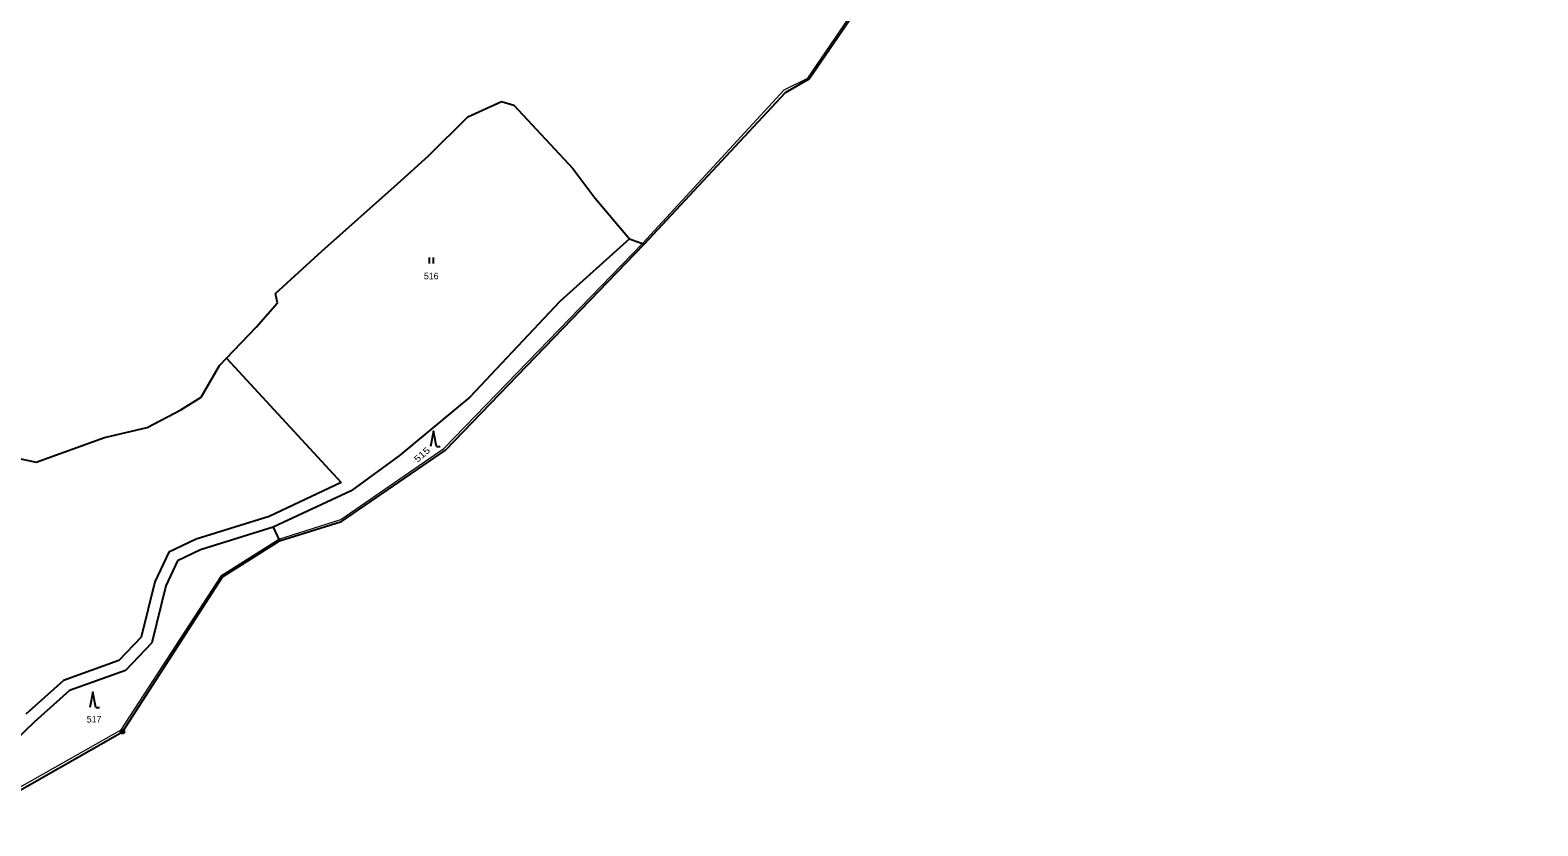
# Model space of a CAD drawing. Extents: x -653193 to -651624, y -1092017 to -1090260.
# Drawn here: x -652015.8 to -651624.2, y -1091342 to -1091135.1 of the extents above; entities that cross this region are included whole.
import ezdxf
from ezdxf.enums import TextEntityAlignment as Align

# ---------------------------------------------------------------- set-up
doc = ezdxf.new("R2010")
doc.units = 0
doc.header["$LTSCALE"] = 0.68
for name, color, linetype, lineweight in [('1', 7, 'Continuous', 25), ('3', 7, 'Continuous', 25), ('4', 7, 'Continuous', 13), ('8', 7, 'Continuous', 25)]:
    doc.layers.add(name, color=color, linetype=linetype, lineweight=lineweight)
doc.layers.add('2', color=7, linetype='Continuous')

msp = doc.modelspace()

# ---------------------------------------------------------------- linework, layer by layer
at = {"layer": '1'}
for p, q in [((-651813.51, -1091147.74), (-651741.09, -1091042.17)), ((-651819.63, -1091151.3), (-651813.51, -1091147.74)), ((-651856.36, -1091190.71), (-651819.63, -1091151.3)), ((-651902.14, -1091157.63), (-651893.36, -1091153.6)), ((-651893.36, -1091153.6), (-651890.18, -1091154.58)), ((-651890.18, -1091154.58), (-651874.87, -1091171.1)), ((-651912.35, -1091167.75), (-651902.14, -1091157.63)), ((-651920.38, -1091175.06), (-651912.35, -1091167.75)), ((-651874.87, -1091171.1), (-651869.11, -1091178.7)), ((-651940.03, -1091192.56), (-651920.38, -1091175.06)), ((-651869.11, -1091178.7), (-651860.16, -1091189.33)), ((-651907.97, -1091244.32), (-651856.36, -1091190.71)), ((-651860.16, -1091189.33), (-651878.25, -1091205.61)), ((-651860.16, -1091189.33), (-651856.36, -1091190.71)), ((-651952.13, -1091203.52), (-651940.03, -1091192.56)), ((-651957.1, -1091212.35), (-651951.61, -1091205.96)), ((-651951.61, -1091205.96), (-651952.13, -1091203.52)), ((-651878.25, -1091205.61), (-651901.63, -1091230.54)), ((-651964.83, -1091220.35), (-651957.1, -1091212.35)), ((-651971.44, -1091230.55), (-651966.66, -1091222.25)), ((-651966.66, -1091222.25), (-651964.83, -1091220.35)), ((-651964.83, -1091220.35), (-651935.01, -1091252.71)), ((-651985.46, -1091238.42), (-651976.7, -1091233.76)), ((-651976.7, -1091233.76), (-651971.44, -1091230.55)), ((-651901.63, -1091230.54), (-651919.86, -1091245.65)), ((-652014.28, -1091247.38), (-651996.53, -1091241)), ((-651996.53, -1091241), (-651985.46, -1091238.42)), ((-652025.75, -1091244.89), (-652014.28, -1091247.38)), ((-651934.93, -1091262.8), (-651907.97, -1091244.32)), ((-651919.86, -1091245.65), (-651932.45, -1091254.89)), ((-651935.01, -1091252.71), (-651953.76, -1091261.49)), ((-651932.45, -1091254.89), (-651952.68, -1091264.29)), ((-651953.76, -1091261.49), (-651972.71, -1091267.39)), ((-651952.68, -1091264.29), (-651971.61, -1091270.19)), ((-651952.68, -1091264.29), (-651951.09, -1091267.9)), ((-651951.09, -1091267.9), (-651934.93, -1091262.8)), ((-651972.71, -1091267.39), (-651979.84, -1091270.8)), ((-651965.88, -1091277.21), (-651951.09, -1091267.9)), ((-651979.84, -1091270.8), (-651983.45, -1091278.53)), ((-651977.58, -1091273.04), (-651980.61, -1091279.53)), ((-651971.61, -1091270.19), (-651977.58, -1091273.04)), ((-651991.83, -1091317.47), (-651965.88, -1091277.21)), ((-651983.45, -1091278.53), (-651986.97, -1091292.87)), ((-651980.61, -1091279.53), (-651984.25, -1091294.36)), ((-651986.97, -1091292.87), (-651992.78, -1091298.95)), ((-651984.25, -1091294.36), (-651991.1, -1091301.53)), ((-651992.78, -1091298.95), (-652007.17, -1091304.16)), ((-652016.85, -1091312.8), (-652007.17, -1091304.16)), ((-651991.1, -1091301.53), (-652005.6, -1091306.78)), ((-652005.6, -1091306.78), (-652014.81, -1091315)), ((-652014.81, -1091315), (-652033.57, -1091333.02)), ((-652034.65, -1091341.96), (-651991.83, -1091317.47))]:
    msp.add_line(p, q, dxfattribs=at)
at = {"layer": '3'}
for p, q in [((-651912.081, -1091195.72), (-651912.081, -1091194.22)), ((-651911.08, -1091195.72), (-651911.08, -1091194.22)), ((-651910.3, -1091243.36), (-651909.304, -1091243.36)), ((-651998.8, -1091311.18), (-651997.804, -1091311.18))]:
    msp.add_line(p, q, dxfattribs=at)
for points in [[(-651910.3, -1091243.36), (-651911.05, -1091239.36), (-651911.8, -1091243.36)], [(-651998.8, -1091311.18), (-651999.55, -1091307.18), (-652000.3, -1091311.18)]]:
    msp.add_lwpolyline(points, dxfattribs=at)
at = {"layer": '4'}
msp.add_lwpolyline([(-652035, -1091341.19), (-651992.17, -1091317.02), (-651966.06, -1091276.8), (-651951.26, -1091267.39), (-651935.12, -1091262.33), (-651908.39, -1091243.89), (-651856.64, -1091190.48), (-651819.93, -1091150.64), (-651813.86, -1091147.54), (-651741.68, -1091041.82), (-651727.21, -1091032.36), (-651665.25, -1091026.44), (-651654.46, -1091023), (-651624.19, -1091007.19), (-651641.09, -1090999.02), (-651650.73, -1090999.02), (-651663.38, -1090999.21)], dxfattribs=at)
at = {"layer": '8'}
for radius in [0.5, 0.0303]:
    msp.add_circle((-651991.83, -1091317.4699), radius, dxfattribs=at)

# ---------------------------------------------------------------- texts
at = {"layer": '2'}
for s, p in [('516', (-651911.649, -1091199.865)), ('517', (-651999.219, -1091315.085))]:
    msp.add_text(s, height=1.7, dxfattribs=at).set_placement(p, align=Align.CENTER)
at = {"layer": '2', "width": 1.2}
msp.add_text('515', height=1.7, rotation=41, dxfattribs=at).set_placement((-651913.4871, -1091246.0838), align=Align.CENTER)

doc.saveas('drawing.dxf')
